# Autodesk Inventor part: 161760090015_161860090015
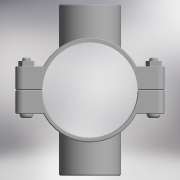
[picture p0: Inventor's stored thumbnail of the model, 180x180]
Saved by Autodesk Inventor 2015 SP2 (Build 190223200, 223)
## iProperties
Created: 2017-05
Part Number: 161760090015_161860090015
Material: Generic
Description: PLASSON DOUBLE SADDLE 90-1.1/2"
Document SubType Name: Modeling
Designer: KIM
Density: 1 g/cm^3
Appearance: Default
Author: KIM
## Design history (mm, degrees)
derived "16176.ipt"
feature "Solid1::16176.ipt"
feature "Solid2::16176.ipt"
tag "TaggingFeature1"
body "Solid1"
body "Solid2"
other parameters: "d0" = 99, "d1" = 141, "d2" = 45, "d4" = 105, "d5" = 0, "d6" = 7.05, "d7" = 141, "d8" = 0.1, "d10" = 0, "d11" = 0.9, "d20" = 0.9, "d23" = 0.9, "d36" = 13, "d37" = 10.4, "d38" = 53, "d39" = 0, "d40" = 3, "d41" = 5, "d42" = 0, "d43" = 8, "d44" = 3, "d45" = 0, "d46" = 0.9, "d52" = 44.845, "d53" = 25, "d54" = 0, "d57" = 0, "d58" = 97.2, "d60" = 0, "d62" = 13, "d63" = 10.4, "d66" = 84.2, "d67" = 162, "d68" = 58.2985, "d69" = 44.845, "d70" = 25, "d71" = 0, "d74" = 0, "d75" = 0.9, "G_" = 44.845, "A_" = 81, "L_" = 141, "L_1" = 105, "l_2" = 25
